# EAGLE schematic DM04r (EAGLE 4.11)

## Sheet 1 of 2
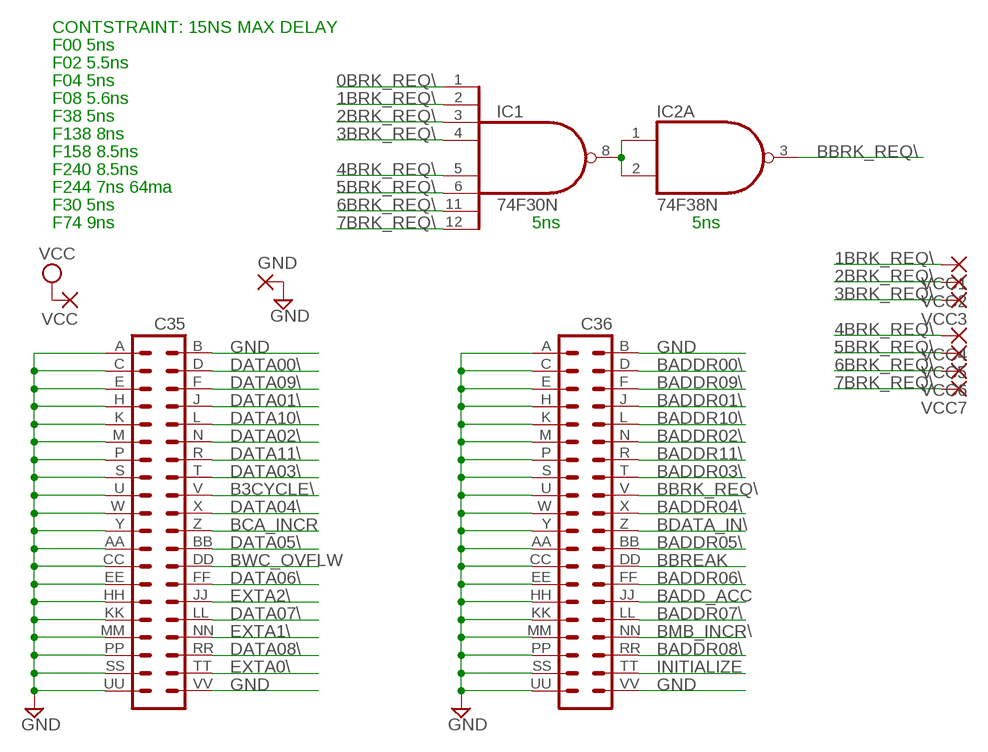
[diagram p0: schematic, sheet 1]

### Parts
C35  DEC40PIN  [DEC40PIN]
C36  DEC40PIN  [DEC40PIN]
GND  2,54/0,8  [2,54/0,8]
IC1  74F30N  74S30N  [DIL14]
IC2  74F38N  [DIL14]
VCC  2,54/0,8  [2,54/0,8]
VCC1  2,54/0,8  [2,54/0,8]
VCC2  2,54/0,8  [2,54/0,8]
VCC3  2,54/0,8  [2,54/0,8]
VCC4  2,54/0,8  [2,54/0,8]
VCC5  2,54/0,8  [2,54/0,8]
VCC6  2,54/0,8  [2,54/0,8]
VCC7  2,54/0,8  [2,54/0,8]

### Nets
0BRK_REQ\: IC1.1(I0) ; also sheet 2
1BRK_REQ\: IC1.2(I1) VCC1.1(P) ; also sheet 2
2BRK_REQ\: IC1.3(I2) VCC2.1(P) ; also sheet 2
3BRK_REQ\: IC1.4(I3) VCC3.1(P) ; also sheet 2
4BRK_REQ\: IC1.5(I4) VCC4.1(P) ; also sheet 2
5BRK_REQ\: IC1.6(I5) VCC5.1(P) ; also sheet 2
6BRK_REQ\: IC1.11(I6) VCC6.1(P) ; also sheet 2
7BRK_REQ\: IC1.12(I7) VCC7.1(P) ; also sheet 2
B3CYCLE\: C35.V
BADD_ACC: C36.JJ
BADDR00\: C36.D ; also sheet 2
BADDR01\: C36.J ; also sheet 2
BADDR02\: C36.N ; also sheet 2
BADDR03\: C36.T ; also sheet 2
BADDR04\: C36.X ; also sheet 2
BADDR05\: C36.BB ; also sheet 2
BADDR06\: C36.FF ; also sheet 2
BADDR07\: C36.LL ; also sheet 2
BADDR08\: C36.RR ; also sheet 2
BADDR09\: C36.F ; also sheet 2
BADDR10\: C36.L ; also sheet 2
BADDR11\: C36.R ; also sheet 2
BBREAK: C36.DD
BBRK_REQ\: C36.V IC2.3(A:O)
BCA_INCR: C35.Z
BDATA_IN\: C36.Z
BMB_INCR\: C36.NN
BWC_OVFLW: C35.DD
DATA00\: C35.D ; also sheet 2
DATA01\: C35.J ; also sheet 2
DATA02\: C35.N ; also sheet 2
DATA03\: C35.T ; also sheet 2
DATA04\: C35.X ; also sheet 2
DATA05\: C35.BB ; also sheet 2
DATA06\: C35.FF ; also sheet 2
DATA07\: C35.LL ; also sheet 2
DATA08\: C35.RR ; also sheet 2
DATA09\: C35.F ; also sheet 2
DATA10\: C35.L ; also sheet 2
DATA11\: C35.R ; also sheet 2
EXTA0\: C35.TT ; also sheet 2
EXTA1\: C35.NN ; also sheet 2
EXTA2\: C35.JJ ; also sheet 2
GND: C35.A C35.AA C35.B C35.C C35.CC C35.E C35.EE C35.H C35.HH C35.K C35.KK C35.M C35.MM C35.P C35.PP C35.S C35.SS C35.U C35.UU C35.VV C35.W C35.Y C36.A C36.AA C36.B C36.C C36.CC C36.E C36.EE C36.H C36.HH C36.K C36.KK C36.M C36.MM C36.P C36.PP C36.S C36.SS C36.U C36.UU C36.VV C36.W C36.Y GND.1(P) ; also sheet 2
INITIALIZE: C36.TT ; also sheet 2
N$1: IC1.8(O) IC2.1(A:I0) IC2.2(A:I1)
VCC: VCC.1(P) ; also sheet 2
Unconnected: IC2.4(B:I0) IC2.5(B:I1) IC2.6(B:O) IC2.8(C:O) IC2.9(C:I0) IC2.10(C:I1) IC2.11(D:O) IC2.12(D:I0) IC2.13(D:I1)

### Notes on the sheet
- CONTSTRAINT: 15NS MAX DELAY
- F00 5ns
- F02 5.5ns
- F04 5ns
- F08 5.6ns
- F38 5ns
- F138 8ns
- F158 8.5ns
- F240 8.5ns
- F244 7ns 64ma
- F30 5ns
- F74 9ns | 5ns | 5ns

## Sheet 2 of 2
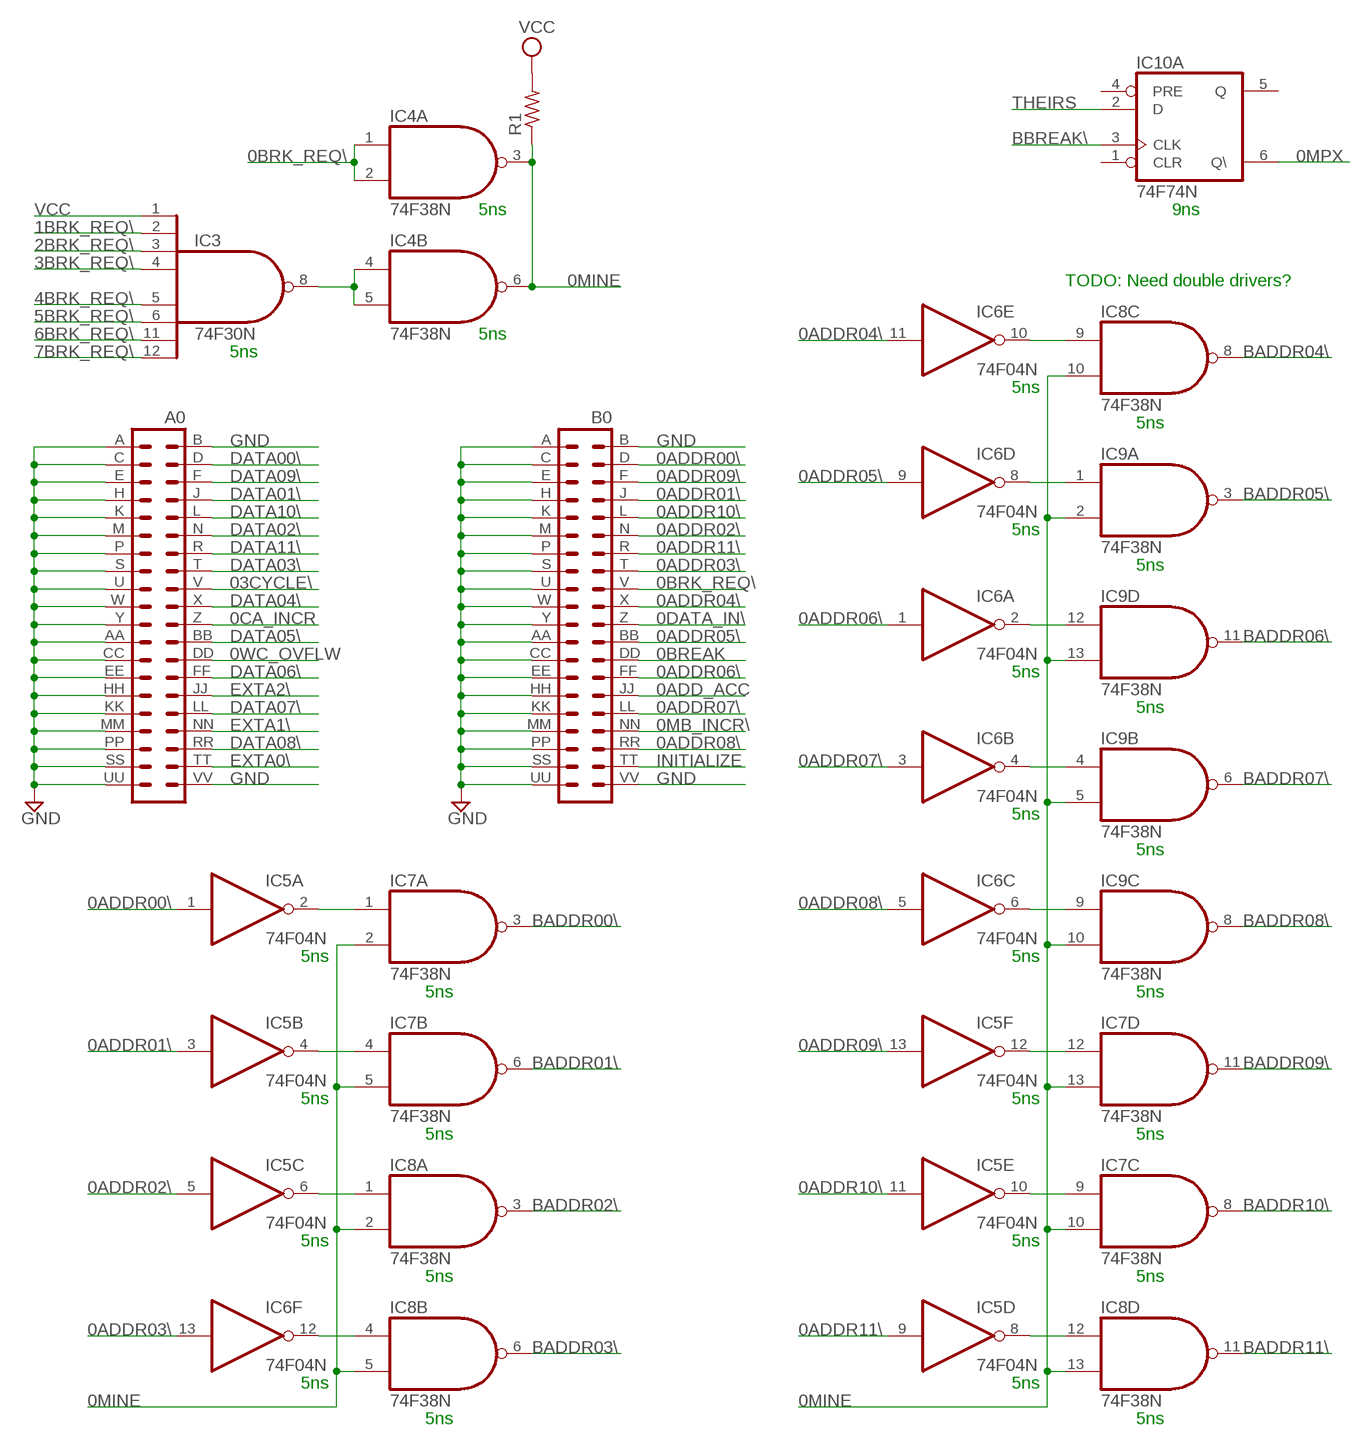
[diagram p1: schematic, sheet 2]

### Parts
A0  DEC40PIN  [DEC40PIN]
B0  DEC40PIN  [DEC40PIN]
IC3  74F30N  74S30N  [DIL14]
IC4  74F38N  [DIL14]
IC5  74F04N  74S04N  [DIL14]
IC6  74F04N  74S04N  [DIL14]
IC7  74F38N  [DIL14]
IC8  74F38N  [DIL14]
IC9  74F38N  [DIL14]
IC10  74F74N  74S74N  [DIL14]
R1  R-US_0207/10  [0207/10]

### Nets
0ADD_ACC: B0.JJ
0ADDR00\: B0.D IC5.1(A:I)
0ADDR01\: B0.J IC5.3(B:I)
0ADDR02\: B0.N IC5.5(C:I)
0ADDR03\: B0.T IC6.13(F:I)
0ADDR04\: B0.X IC6.11(E:I)
0ADDR05\: B0.BB IC6.9(D:I)
0ADDR06\: B0.FF IC6.1(A:I)
0ADDR07\: B0.LL IC6.3(B:I)
0ADDR08\: B0.RR IC6.5(C:I)
0ADDR09\: B0.F IC5.13(F:I)
0ADDR10\: B0.L IC5.11(E:I)
0ADDR11\: B0.R IC5.9(D:I)
0BREAK: B0.DD
0BRK_REQ\: B0.V IC4.1(A:I0) IC4.2(A:I1) ; also sheet 1
0CA_INCR: A0.Z
0DATA_IN\: B0.Z
0MB_INCR\: B0.NN
0MINE: IC4.3(A:O) IC4.6(B:O) IC7.2(A:I1) IC7.5(B:I1) IC7.10(C:I1) IC7.13(D:I1) IC8.2(A:I1) IC8.5(B:I1) IC8.10(C:I1) IC8.13(D:I1) IC9.2(A:I1) IC9.5(B:I1) IC9.10(C:I1) IC9.13(D:I1) R1.1
0MPX: IC10.6(A:Q\)
0WC_OVFLW: A0.DD
1BRK_REQ\: IC3.2(I1) ; also sheet 1
2BRK_REQ\: IC3.3(I2) ; also sheet 1
3BRK_REQ\: IC3.4(I3) ; also sheet 1
03CYCLE\: A0.V
4BRK_REQ\: IC3.5(I4) ; also sheet 1
5BRK_REQ\: IC3.6(I5) ; also sheet 1
6BRK_REQ\: IC3.11(I6) ; also sheet 1
7BRK_REQ\: IC3.12(I7) ; also sheet 1
BADDR00\: IC7.3(A:O) ; also sheet 1
BADDR01\: IC7.6(B:O) ; also sheet 1
BADDR02\: IC8.3(A:O) ; also sheet 1
BADDR03\: IC8.6(B:O) ; also sheet 1
BADDR04\: IC8.8(C:O) ; also sheet 1
BADDR05\: IC9.3(A:O) ; also sheet 1
BADDR06\: IC9.11(D:O) ; also sheet 1
BADDR07\: IC9.6(B:O) ; also sheet 1
BADDR08\: IC9.8(C:O) ; also sheet 1
BADDR09\: IC7.11(D:O) ; also sheet 1
BADDR10\: IC7.8(C:O) ; also sheet 1
BADDR11\: IC8.11(D:O) ; also sheet 1
BBREAK\: IC10.3(A:CLK)
DATA00\: A0.D ; also sheet 1
DATA01\: A0.J ; also sheet 1
DATA02\: A0.N ; also sheet 1
DATA03\: A0.T ; also sheet 1
DATA04\: A0.X ; also sheet 1
DATA05\: A0.BB ; also sheet 1
DATA06\: A0.FF ; also sheet 1
DATA07\: A0.LL ; also sheet 1
DATA08\: A0.RR ; also sheet 1
DATA09\: A0.F ; also sheet 1
DATA10\: A0.L ; also sheet 1
DATA11\: A0.R ; also sheet 1
EXTA0\: A0.TT ; also sheet 1
EXTA1\: A0.NN ; also sheet 1
EXTA2\: A0.JJ ; also sheet 1
GND: A0.A A0.AA A0.B A0.C A0.CC A0.E A0.EE A0.H A0.HH A0.K A0.KK A0.M A0.MM A0.P A0.PP A0.S A0.SS A0.U A0.UU A0.VV A0.W A0.Y B0.A B0.AA B0.B B0.C B0.CC B0.E B0.EE B0.H B0.HH B0.K B0.KK B0.M B0.MM B0.P B0.PP B0.S B0.SS B0.U B0.UU B0.VV B0.W B0.Y ; also sheet 1
INITIALIZE: B0.TT ; also sheet 1
N$3: IC6.10(E:O) IC8.9(C:I0)
N$4: IC3.8(O) IC4.4(B:I0) IC4.5(B:I1)
N$5: IC6.8(D:O) IC9.1(A:I0)
N$7: IC6.2(A:O) IC9.12(D:I0)
N$9: IC6.4(B:O) IC9.4(B:I0)
N$11: IC6.6(C:O) IC9.9(C:I0)
N$13: IC5.12(F:O) IC7.12(D:I0)
N$15: IC5.10(E:O) IC7.9(C:I0)
N$17: IC5.8(D:O) IC8.12(D:I0)
N$19: IC5.2(A:O) IC7.1(A:I0)
N$21: IC5.4(B:O) IC7.4(B:I0)
N$23: IC5.6(C:O) IC8.1(A:I0)
N$25: IC6.12(F:O) IC8.4(B:I0)
THEIRS: IC10.2(A:D)
VCC: IC3.1(I0) R1.2 ; also sheet 1
Unconnected: IC4.8(C:O) IC4.9(C:I0) IC4.10(C:I1) IC4.11(D:O) IC4.12(D:I0) IC4.13(D:I1) IC10.1(A:CLR) IC10.4(A:PRE) IC10.5(A:Q) IC10.8(B:Q\) IC10.9(B:Q) IC10.10(B:PRE) IC10.11(B:CLK) IC10.12(B:D) IC10.13(B:CLR)

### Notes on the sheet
- 5ns | 9ns
- TODO: Need double drivers?
- 5ns
- 5ns
- 5ns
- 5ns
- 5ns
- 5ns
- 5ns
- 5ns
- 5ns
- 5ns
- 5ns | 5ns
- 5ns | 5ns
- 5ns | 5ns
- 5ns | 5ns
- 5ns | 5ns
- 5ns | 5ns
- 5ns | 5ns
- 5ns | 5ns

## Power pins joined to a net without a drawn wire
GND: IC1.7(GND) IC2.7(P:GND) IC3.7(GND) IC4.7(P:GND) IC5.7(P:GND) IC6.7(P:GND) IC7.7(P:GND) IC8.7(P:GND) IC9.7(P:GND) IC10.7(P:GND)
VCC: IC1.14(VCC) IC2.14(P:VCC) IC3.14(VCC) IC4.14(P:VCC) IC5.14(P:VCC) IC6.14(P:VCC) IC7.14(P:VCC) IC8.14(P:VCC) IC9.14(P:VCC) IC10.14(P:VCC)

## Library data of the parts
A0 B0 C35 C36 = dec-con:DEC40PIN: PIN HEADER
GND VCC VCC1-VCC7 = wirepad:2,54/0,8: THROUGH-HOLE PAD
IC1 IC3 = 74xx-jameco:74*30: 8-input NAND gate
IC2 IC4 IC7-IC9 = 74xx-jameco:74*38: Quad 2-input NAND gate, open collector output
IC5 IC6 = 74xx-jameco:74*04: Hex INVERTER
IC10 = 74xx-jameco:74*74: Dual D type positive edge triggered FLIP FLOP, preset and clear
R1 = rcl:R-US_: RESISTOR, American symbol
